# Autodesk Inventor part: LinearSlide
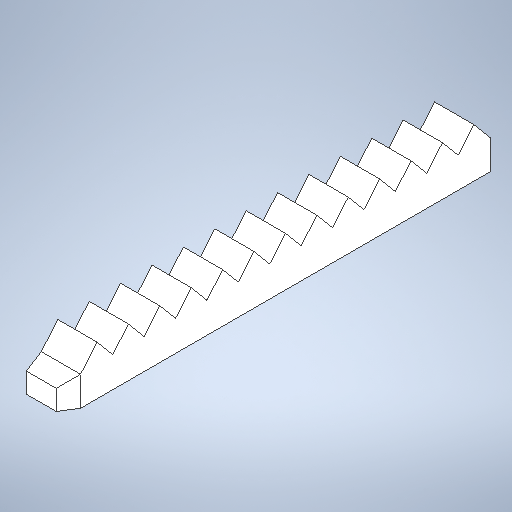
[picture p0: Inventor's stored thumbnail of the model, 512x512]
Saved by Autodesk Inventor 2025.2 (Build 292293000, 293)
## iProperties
Created: 2025-09
Part Number: LinearSlide
Material: Generic
Document SubType Name: Modeling
Designer: tyler
Density: 1 g/cm^3
Appearance: Default
Author: tyler
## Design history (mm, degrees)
sketch "Sketch1"
  geometry: 1 further point
sketch "Sketch2"
  geometry: L1 (2.381, 31.555)-(-2.381, 31.555); L2 (-2.381, 31.555)-(-2.381, -31.945); L3 (-2.381, -31.945)-(2.381, -31.945); L4 (2.381, 31.555)-(-2.381, -31.945); L5 (-2.381, 31.555)-(2.381, -31.945); L6 (2.381, 31.555)-(5.556, 31.555); L7 (5.556, 31.555)-(5.556, 17.667); L8 (2.381, 31.555)-(5.556, 28.891); L9 (2.381, 31.555)-(6.526, 31.555); L10 (5.556, 28.891)-(2.381, 26.227); L11 (2.381, 26.475)-(5.556, 23.811); L12 (5.556, 23.811)-(2.381, 21.147); L13 (2.381, 21.395)-(5.556, 18.731); L14 (5.556, 18.731)-(2.381, 16.067); L15 (2.381, 16.315)-(5.556, 13.651); L16 (5.556, 13.651)-(2.381, 10.987); L17 (2.381, 11.235)-(5.556, 8.571); L18 (5.556, 8.571)-(2.381, 5.907); L19 (2.381, 6.155)-(5.556, 3.491); L20 (5.556, 3.491)-(2.381, 0.827); L21 (2.381, 1.075)-(5.556, -1.589); L22 (5.556, -1.589)-(2.381, -4.253); L23 (2.381, -4.005)-(5.556, -6.669); L24 (5.556, -6.669)-(2.381, -9.333); L25 (2.381, -9.085)-(5.556, -11.749); L26 (5.556, -11.749)-(2.381, -14.413); L27 (2.381, -14.165)-(5.556, -16.829); L28 (5.556, -16.829)-(2.381, -19.493); L29 (2.381, -19.245)-(5.556, -21.909); L30 (5.556, -21.909)-(2.381, -24.573); L31 (2.381, -24.325)-(5.556, -26.989); L32 (5.556, -26.989)-(2.381, -29.653); L33 (2.381, -29.405)-(5.556, -32.069); L34 (5.556, -32.069)-(2.381, -34.733); L35 (-2.381, -31.945)-(-2.381, -34.733); L36 (-2.381, -34.733)-(2.381, -34.733); 37 further points
  constraints: 72 end point, 36 vertical alignment, 25 parallel, 3 horizontal, 3 perpendicular, 2 midpoint, 2 vertical, 1 equal length, 1 point on line, 4 other
  dimensions: "d0" = 4.7625 distance of L3.end L2.end; "d1" = 63.5 distance of L2.end L1.end; "d2" = 3.175 distance of L1.start L6.end; "d3" = 40 deg angle of L8 L9; "d6" = 5.08 distance of L1.start L11.start; "d20" = 50 deg angle of L10 L7
extrude "Extrusion1" new body sketch "Sketch2" distance "d11" = 6.35; taper "d12" = 0 deg
sketch "Sketch3"
  geometry: L1 (0, 0)-(3.175, 0); L2 (0, 0)-(6.35, 0) reference; L3 (0, 4.763)-(6.35, 4.763); L4 (6.35, 4.763)-(6.35, 0); L5 (6.35, 0)-(0, 0); L6 (0, 0)-(0, 4.763); L7 (0, 4.763)-(6.35, 0); L8 (6.35, 4.763)-(0, 0); 3 further points
  constraints: 14 end point, 3 midpoint, 2 parallel, 1 horizontal, 1 perpendicular
  dimensions: "d13" = 6.35 distance of L2.end L5.end; "d14" = 4.7625 distance of L3.end L2.end
extrude "Extrusion2" join sketch "Sketch3" distance "d15" = 3.175; taper "d16" = 0 deg
chamfer "Chamfer1" distance "d17" = 0.762; stored, may be unused: second distance "d18" = 3.175, angle "d19" = 45 deg
body "Solid1"
node "Sketch Rectangular Pattern1" dims "d6" = 5.08, "d9" = 25.4
